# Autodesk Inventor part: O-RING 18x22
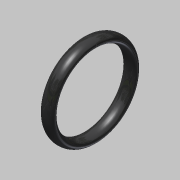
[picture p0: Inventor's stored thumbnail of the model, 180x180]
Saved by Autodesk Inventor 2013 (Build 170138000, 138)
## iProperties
Created: 2020-02
Part Number: O-RING 18x22
Material: 고무
Document SubType Name: Modeling
Designer: mduedu
Density: 1 g/cm^3
Author: mduedu
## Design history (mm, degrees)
sketch "스케치1"
  geometry: L1 (-2.24, 0)-(2.24, 0) reference; L2 (-1.6, 10)-(1.6, 10); L3 (0, 11)-(0, 9); 6 further points; 1 other entity
  constraints: 4 coincident, 4 end point, 2 horizontal, 2 midpoint, 1 vertical, 1 vertical alignment, 6 other
  dimensions: "d0" = 18 diameter of point (0, 9) L1; "d1" = 22 diameter of point (0, 11) L1; "d2" = 1.6 distance from line of point (1.6, 10) L3
revolve "회전1" sketch "스케치1" stored, may be unused: angle "d3" = 90 deg
node "솔리드1"
